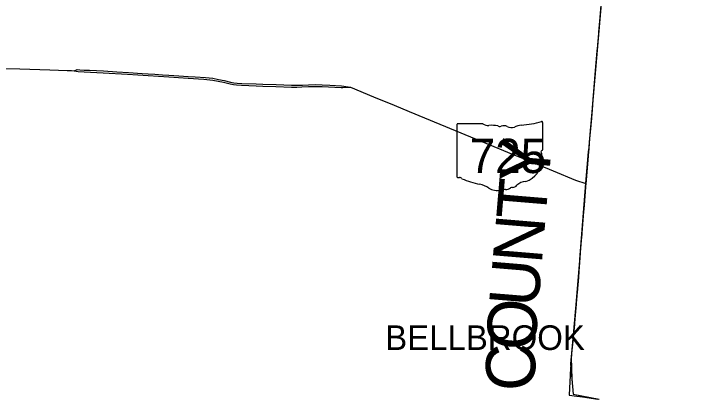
# Model space of a CAD drawing. Extents: x 0 to 34, y 0 to 22.
# Drawn here: x 5.4654 to 5.6883, y 14.3807 to 14.5058 of the extents above; entities that cross this region are included whole.
import ezdxf

# ---------------------------------------------------------------- set-up
doc = ezdxf.new("R2010")
doc.units = 0
for name, color, linetype in [('GM_X_Corporation', 7, 'Continuous'), ('GM_X_Corporation_Text', 7, 'Continuous'), ('GM_X_County', 7, 'Continuous'), ('GM_X_County_Text', 7, 'Continuous'), ('GM_X_State_Location', 7, 'Continuous'), ('GM_X_State_Route', 7, 'Continuous'), ('GM_X_State_Shield', 7, 'Continuous'), ('SC_Scratch1', 7, 'Continuous')]:
    doc.layers.add(name, color=color, linetype=linetype)

msp = doc.modelspace()

# ---------------------------------------------------------------- linework, layer by layer
at = {"layer": 'GM_X_Corporation'}
msp.add_lwpolyline([(5.65716, 14.5118), (5.65609, 14.4998), (5.65609, 14.49976), (5.65606, 14.49946), (5.65581, 14.49645), (5.65557, 14.49358), (5.65504, 14.4873), (5.65378, 14.47239), (5.65377, 14.47221), (5.65354, 14.46949), (5.65308, 14.46389), (5.65287, 14.46138), (5.65284, 14.46105), (5.65282, 14.46085), (5.6527, 14.45945), (5.65192, 14.45026), (5.65188, 14.44971), (5.65184, 14.44922), (5.65136, 14.44333), (5.65109, 14.43996), (5.65089, 14.43744), (5.65078, 14.43614), (5.65059, 14.4338), (5.65053, 14.43304), (5.65025, 14.42958), (5.64999, 14.4261), (5.64996, 14.42569), (5.64993, 14.4253), (5.64972, 14.42263), (5.64971, 14.4225), (5.64953, 14.42016), (5.6495, 14.41977), (5.64947, 14.41935), (5.64921, 14.41596), (5.64918, 14.41555), (5.64916, 14.41531), (5.64891, 14.41245), (5.64883, 14.41153), (5.6488, 14.41113), (5.64849, 14.40754), (5.64825, 14.40502), (5.64822, 14.40474), (5.64821, 14.40466), (5.6482, 14.40456), (5.6482, 14.40453), (5.64798, 14.40225), (5.64789, 14.4013), (5.6478, 14.40031), (5.64756, 14.39788), (5.64749, 14.39714), (5.64727, 14.39484), (5.64724, 14.39449), (5.64715, 14.39358), (5.64708, 14.39218), (5.64705, 14.39168), (5.64702, 14.3912), (5.647, 14.39077), (5.64698, 14.39041), (5.64684, 14.38786), (5.6466, 14.38366), (5.64648, 14.38144), (5.64898, 14.38109), (5.65087, 14.38083), (5.65583, 14.38013)], dxfattribs=at)
at = {"layer": 'GM_X_County'}
msp.add_lwpolyline([(5.65784, 14.52043), (5.65588, 14.49684), (5.65414, 14.47652), (5.6541, 14.47599), (5.65365, 14.47045), (5.65348, 14.46897), (5.65279, 14.46109), (5.65275, 14.46093), (5.65273, 14.46075), (5.65188, 14.45052), (5.6499, 14.42568), (5.64953, 14.41974), (5.64696, 14.39166), (5.64782, 14.38178), (5.6563, 14.38009)], dxfattribs=at)
at = {"layer": 'GM_X_State_Route'}
msp.add_line((5.46152, 14.48795), (5.46741, 14.48777), dxfattribs=at)
for points in [[(5.46741, 14.48777), (5.47725, 14.48747), (5.48286, 14.48728), (5.48429, 14.48722)], [(5.48514, 14.48718), (5.48616, 14.48754), (5.48697, 14.48751), (5.48842, 14.48743), (5.49016, 14.48734), (5.49471, 14.48711), (5.49908, 14.48687), (5.50283, 14.48662), (5.50731, 14.48634), (5.50924, 14.48621), (5.51138, 14.48606), (5.51397, 14.48589), (5.51599, 14.48576), (5.5192, 14.48554), (5.52228, 14.48533), (5.52458, 14.48519), (5.52798, 14.48495), (5.53039, 14.48474), (5.53215, 14.48438), (5.53398, 14.48398), (5.53607, 14.48347), (5.5372, 14.48327), (5.53825, 14.48313), (5.53977, 14.48304), (5.54444, 14.48287), (5.54664, 14.48278), (5.55095, 14.48265), (5.55602, 14.48246), (5.55775, 14.48244), (5.55955, 14.48251), (5.56155, 14.48261), (5.56371, 14.48268), (5.56597, 14.48264), (5.56847, 14.48251), (5.57229, 14.48224), (5.57523, 14.48178)], [(5.48429, 14.48722), (5.48514, 14.48718), (5.48643, 14.48696), (5.48837, 14.48686), (5.4946, 14.48652), (5.50249, 14.48606), (5.50925, 14.48563), (5.51594, 14.48518), (5.5223, 14.48476), (5.52735, 14.48442), (5.53034, 14.48415), (5.53207, 14.48383), (5.53382, 14.48342), (5.53596, 14.4829), (5.53711, 14.48268), (5.53809, 14.48256), (5.53968, 14.48247), (5.54444, 14.48227), (5.5466, 14.4822), (5.55085, 14.48204), (5.55594, 14.48187), (5.55777, 14.48187), (5.55939, 14.48189), (5.5615, 14.48202), (5.56358, 14.48208), (5.56594, 14.48209), (5.57219, 14.48174), (5.5727, 14.48175)], [(5.5727, 14.48175), (5.57523, 14.48178), (5.58274, 14.4787), (5.58943, 14.47597), (5.59433, 14.47392), (5.61935, 14.46361), (5.62772, 14.46008), (5.63373, 14.45769), (5.6413, 14.45459), (5.64856, 14.45152), (5.6519, 14.45047)]]:
    msp.add_lwpolyline(points, dxfattribs=at)
at = {"layer": 'GM_X_State_Shield'}
for p, q in [((5.61836, 14.4699), (5.61017, 14.4699)), ((5.63787, 14.46144), (5.63787, 14.47032)), ((5.60989, 14.46961), (5.60989, 14.45262)), ((5.63786, 14.46144), (5.63787, 14.46144))]:
    msp.add_line(p, q, dxfattribs=at)
for centre, major_axis, start_param, end_param in [((5.61021, 14.46965), (0.000324, 0), 1.712693, 3.28349), ((5.62031, 14.47187), (0.00314, 0), 4.042523, 4.731795), ((5.6279, 14.49306), (0.02966, 0), 4.814394, 5.042369), ((5.63756, 14.47036), (0.000311, 0), 6.141152, 7.989035), ((5.62135, 14.46037), (0.01128, 0), 1.404758, 1.657858), ((5.62392, 14.46973), (0.000907, 0), 3.836095, 5.185415), ((5.62525, 14.46777), (0.00189, 0), 0.950623, 2.079405), ((5.62768, 14.47046), (0.00227, 0), 4.081561, 5.145723), ((5.63169, 14.46471), (0.00597, 0), 1.699011, 2.107814), ((5.63779, 14.46079), (0.000482, 0), 1.883978, 3.671073), ((5.63753, 14.4614), (0.000333, 0), 5.05454, 6.418171), ((5.63898, 14.45772), (0.0021, 0), 2.387724, 3.262537), ((5.63473, 14.45966), (0.00289, 0), 5.934695, 6.695948), ((5.62956, 14.45659), (0.00742, 0), 5.101752, 6.440018), ((5.61022, 14.45259), (0.000327, 0), 3.00124, 4.508301), ((5.61027, 14.45433), (0.00249, 0), 4.665946, 4.897461), ((5.61078, 14.45164), (0.0009, 0), 0.519207, 1.627899), ((5.62213, 14.4669), (0.02142, 0), 4.195997, 4.488961), ((5.61575, 14.44499), (0.0067, 0), 0.823519, 1.323587), ((5.62754, 14.45098), (0.0024, 0), 4.937069, 5.64225), ((5.63269, 14.44786), (0.00406, 0), 1.647645, 2.488434), ((5.623, 14.45156), (0.00425, 0), 4.026481, 4.996735), ((5.62545, 14.44569), (0.00349, 0), 1.495662, 1.94098), ((5.62577, 14.45029), (0.00227, 0), 4.691044, 5.507374), ((5.62782, 14.44864), (0.000638, 0), 1.147584, 2.315152)]:
    msp.add_ellipse(centre, major_axis=major_axis, ratio=0.8, start_param=start_param, end_param=end_param, dxfattribs=at)
at = {"layer": 'SC_Scratch1'}
msp.add_lwpolyline([(5.68829, 14.88472), (5.67064, 14.67069), (5.66847, 14.64204), (5.66626, 14.6271), (5.66463, 14.59984), (5.66169, 14.56551), (5.65722, 14.51297), (5.65245, 14.45733), (5.65049, 14.43309), (5.64861, 14.40966), (5.64714, 14.39366), (5.64739, 14.38669), (5.64782, 14.38178), (5.65607, 14.38013)], dxfattribs=at)

# ---------------------------------------------------------------- texts
at = {"layer": 'GM_X_Corporation_Text'}
msp.add_text('BELLBROOK', height=0.008037, rotation=0, dxfattribs=at).set_placement((5.58652, 14.39614))
at = {"layer": 'GM_X_County_Text'}
for s, rotation, p in [('Y', 85.0528, (5.63974, 14.45006)), ('T', 85.231, (5.63874, 14.43809)), ('N', 85.2339, (5.63756, 14.42393)), ('U', 85.2612, (5.63638, 14.40976)), ('O', 85.9265, (5.63538, 14.39563)), ('C', 90.9724, (5.63561, 14.38292))]:
    msp.add_text(s, height=0.01607, rotation=rotation, dxfattribs=at).set_placement(p)
at = {"layer": 'GM_X_State_Location'}
msp.add_text('725', height=0.0000161, rotation=0, dxfattribs=at).set_placement((5.61789, 14.45882))
for s, p in [('s', (5.62357, 14.45999)), ('r', (5.62356, 14.45999))]:
    msp.add_text(s, height=0.0000161, dxfattribs=at).set_placement(p)
at = {"layer": 'GM_X_State_Shield'}
msp.add_text('725', height=0.011189, dxfattribs=at).set_placement((5.61406, 14.45382))

doc.saveas('drawing.dxf')
